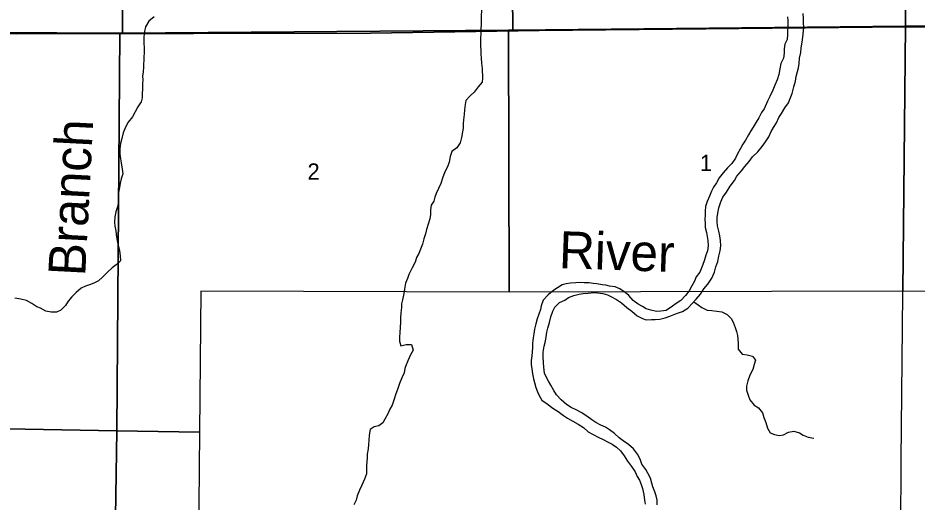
# Model space of a CAD drawing. Extents: x 1772825 to 1773716, y 1138558 to 1139032.
# Drawn here: x 1772826.846 to 1772827.997, y 1138560.526 to 1138561.147 of the extents above; entities that cross this region are included whole.
import ezdxf

# ---------------------------------------------------------------- set-up
doc = ezdxf.new("R2010")
doc.units = 0
for name, color, linetype in [('GM_X_Major_River', 7, 'Continuous'), ('GM_X_Major_River_Text', 7, 'Continuous'), ('GM_X_Minor_River', 7, 'Continuous'), ('GM_X_Minor_River_Text', 7, 'Continuous'), ('GM_X_Section', 7, 'Continuous'), ('GM_X_Section_Text', 7, 'Continuous'), ('GM_X_Township', 7, 'Continuous')]:
    doc.layers.add(name, color=color, linetype=linetype)

msp = doc.modelspace()

# ---------------------------------------------------------------- linework, layer by layer
at = {"layer": 'GM_X_Major_River'}
for points in [[(1772827.6457, 1138560.7616), (1772827.6506, 1138560.76), (1772827.6572, 1138560.7604), (1772827.662, 1138560.7603), (1772827.6682, 1138560.7607), (1772827.6749, 1138560.7625), (1772827.6806, 1138560.7646), (1772827.6873, 1138560.7672), (1772827.692, 1138560.7688), (1772827.697, 1138560.7709), (1772827.7038, 1138560.775), (1772827.7096, 1138560.7808), (1772827.7145, 1138560.7867), (1772827.7199, 1138560.7931), (1772827.7245, 1138560.7999), (1772827.7293, 1138560.8059), (1772827.7346, 1138560.8135), (1772827.7379, 1138560.8212), (1772827.7399, 1138560.828), (1772827.7424, 1138560.835), (1772827.7436, 1138560.8415), (1772827.7453, 1138560.8485), (1772827.746, 1138560.8551), (1772827.7456, 1138560.8618), (1772827.7449, 1138560.8677), (1772827.7434, 1138560.8737), (1772827.742, 1138560.8804), (1772827.7414, 1138560.8855), (1772827.7415, 1138560.8914), (1772827.7423, 1138560.8967), (1772827.7437, 1138560.9037), (1772827.7462, 1138560.9113), (1772827.7489, 1138560.9171), (1772827.7535, 1138560.9239), (1772827.7581, 1138560.9315), (1772827.7635, 1138560.9388), (1772827.7667, 1138560.9443), (1772827.7725, 1138560.9511), (1772827.7767, 1138560.9564), (1772827.7826, 1138560.9632), (1772827.7866, 1138560.9692), (1772827.7935, 1138560.9756), (1772827.7991, 1138560.9824), (1772827.8033, 1138560.9882), (1772827.8075, 1138560.9947), (1772827.8108, 1138561.0015), (1772827.8137, 1138561.0068), (1772827.8173, 1138561.0128), (1772827.8204, 1138561.0196), (1772827.8239, 1138561.0245), (1772827.8281, 1138561.0317), (1772827.8329, 1138561.0383), (1772827.835, 1138561.0436), (1772827.8373, 1138561.0504), (1772827.8395, 1138561.0587), (1772827.8416, 1138561.0659), (1772827.8426, 1138561.0722), (1772827.8444, 1138561.0782), (1772827.8454, 1138561.0832), (1772827.8465, 1138561.0887), (1772827.8471, 1138561.0953), (1772827.8485, 1138561.1027), (1772827.8491, 1138561.1089), (1772827.8501, 1138561.1158), (1772827.8513, 1138561.1224), (1772827.8524, 1138561.1347), (1772827.8522, 1138561.1412), (1772827.8521, 1138561.1467), (1772827.8514, 1138561.1527)], [(1772827.8316, 1138561.1487), (1772827.8319, 1138561.1434), (1772827.8321, 1138561.1354), (1772827.8317, 1138561.1307), (1772827.8316, 1138561.126), (1772827.831, 1138561.1193), (1772827.8281, 1138561.1133), (1772827.8273, 1138561.1076), (1772827.8271, 1138561.1017), (1772827.8263, 1138561.0955), (1772827.823, 1138561.0885), (1772827.8218, 1138561.0818), (1772827.8204, 1138561.0746), (1772827.8181, 1138561.0678), (1772827.8152, 1138561.0608), (1772827.8129, 1138561.0544), (1772827.8088, 1138561.0463), (1772827.806, 1138561.0404), (1772827.8017, 1138561.0306), (1772827.7983, 1138561.0257), (1772827.7946, 1138561.0189), (1772827.7915, 1138561.0136), (1772827.7877, 1138561.0071), (1772827.7846, 1138561.0022), (1772827.7817, 1138560.9973), (1772827.7777, 1138560.9905), (1772827.7741, 1138560.9852), (1772827.7714, 1138560.9798), (1772827.7673, 1138560.973), (1772827.7648, 1138560.9675), (1772827.7602, 1138560.9605), (1772827.7547, 1138560.9547), (1772827.7493, 1138560.9486), (1772827.7441, 1138560.9422), (1772827.7405, 1138560.9356), (1772827.7366, 1138560.9301), (1772827.7341, 1138560.925), (1772827.7318, 1138560.9186), (1772827.7285, 1138560.9118), (1772827.7264, 1138560.9054), (1772827.7262, 1138560.8993), (1772827.7259, 1138560.8944), (1772827.7255, 1138560.8892), (1772827.7259, 1138560.8835), (1772827.7262, 1138560.8784), (1772827.7277, 1138560.8721), (1772827.7288, 1138560.8668), (1772827.7295, 1138560.8617), (1772827.7298, 1138560.8551), (1772827.729, 1138560.8486), (1772827.7271, 1138560.8431), (1772827.7251, 1138560.8369), (1772827.7226, 1138560.8295), (1772827.7191, 1138560.821), (1772827.7145, 1138560.815), (1772827.7122, 1138560.8098), (1772827.7088, 1138560.8038), (1772827.7055, 1138560.7974), (1772827.7009, 1138560.7913), (1772827.695, 1138560.7849), (1772827.6891, 1138560.781), (1772827.6841, 1138560.7774), (1772827.6761, 1138560.772), (1772827.6691, 1138560.7713), (1772827.6636, 1138560.7708), (1772827.6566, 1138560.7723)], [(1772827.6566, 1138560.7723), (1772827.6507, 1138560.7743), (1772827.6458, 1138560.777), (1772827.6403, 1138560.78), (1772827.6337, 1138560.785), (1772827.6284, 1138560.7913), (1772827.6235, 1138560.7952), (1772827.6169, 1138560.7999), (1772827.6109, 1138560.8023), (1772827.6037, 1138560.8031), (1772827.5987, 1138560.8043), (1772827.594, 1138560.805), (1772827.5872, 1138560.8062), (1772827.5824, 1138560.8068), (1772827.5775, 1138560.8073), (1772827.5711, 1138560.8075), (1772827.5652, 1138560.8079), (1772827.5604, 1138560.8074), (1772827.5534, 1138560.8071), (1772827.5479, 1138560.8062), (1772827.5431, 1138560.8049), (1772827.537, 1138560.8009), (1772827.5321, 1138560.7979), (1772827.525, 1138560.7921), (1772827.5187, 1138560.7851), (1772827.516, 1138560.7781), (1772827.515, 1138560.7732), (1772827.5131, 1138560.7675), (1772827.511, 1138560.7615), (1772827.5092, 1138560.755), (1772827.5074, 1138560.7482), (1772827.5066, 1138560.7422), (1772827.5058, 1138560.7368), (1772827.505, 1138560.73), (1772827.5048, 1138560.7249), (1772827.5046, 1138560.7185), (1772827.504, 1138560.7137), (1772827.5033, 1138560.7078), (1772827.5033, 1138560.7027), (1772827.5042, 1138560.6972), (1772827.5051, 1138560.6909), (1772827.5062, 1138560.6845), (1772827.5073, 1138560.6795), (1772827.5092, 1138560.6731), (1772827.5112, 1138560.6679), (1772827.5136, 1138560.6628), (1772827.517, 1138560.6571), (1772827.5236, 1138560.6523), (1772827.531, 1138560.6469), (1772827.5376, 1138560.6427), (1772827.5448, 1138560.6372), (1772827.5497, 1138560.6339), (1772827.5567, 1138560.6302), (1772827.5633, 1138560.6264), (1772827.5701, 1138560.6222), (1772827.5763, 1138560.6166), (1772827.5827, 1138560.613), (1772827.5888, 1138560.6097), (1772827.5956, 1138560.6066), (1772827.6018, 1138560.6032), (1772827.6071, 1138560.6006), (1772827.6126, 1138560.5968), (1772827.6176, 1138560.592), (1772827.6225, 1138560.5855), (1772827.6267, 1138560.5789), (1772827.6319, 1138560.5722), (1772827.6364, 1138560.5651), (1772827.6388, 1138560.5592), (1772827.642, 1138560.5543), (1772827.6441, 1138560.5488), (1772827.6457, 1138560.5436), (1772827.6476, 1138560.5362), (1772827.6485, 1138560.529), (1772827.649, 1138560.5235)], [(1772827.6646, 1138560.5228), (1772827.6644, 1138560.5289), (1772827.6635, 1138560.5344), (1772827.6617, 1138560.5395), (1772827.6592, 1138560.546), (1772827.6579, 1138560.5508), (1772827.6559, 1138560.5572), (1772827.6527, 1138560.5635), (1772827.6499, 1138560.5683), (1772827.6448, 1138560.5751), (1772827.6426, 1138560.5812), (1772827.6396, 1138560.5877), (1772827.6344, 1138560.5946), (1772827.6278, 1138560.6003), (1772827.621, 1138560.6049), (1772827.6157, 1138560.6089), (1772827.61, 1138560.6145), (1772827.6036, 1138560.6189), (1772827.5985, 1138560.6223), (1772827.5923, 1138560.625), (1772827.586, 1138560.6285), (1772827.5809, 1138560.632), (1772827.5743, 1138560.6366), (1772827.5672, 1138560.6414), (1772827.5615, 1138560.6444), (1772827.5545, 1138560.6477), (1772827.5486, 1138560.6514), (1772827.5417, 1138560.6575), (1772827.5358, 1138560.664), (1772827.5323, 1138560.6693), (1772827.5282, 1138560.6762), (1772827.5252, 1138560.6813), (1772827.5225, 1138560.6868), (1772827.5203, 1138560.6918), (1772827.5192, 1138560.6992), (1772827.5189, 1138560.7055), (1772827.5184, 1138560.7127), (1772827.5184, 1138560.7185), (1772827.5198, 1138560.7261), (1772827.5214, 1138560.7326), (1772827.5222, 1138560.7384), (1772827.5233, 1138560.7441), (1772827.5247, 1138560.7494), (1772827.5267, 1138560.7568), (1772827.5284, 1138560.7638), (1772827.5309, 1138560.7712), (1772827.5334, 1138560.7761), (1772827.5394, 1138560.7821), (1772827.5464, 1138560.7853), (1772827.5512, 1138560.7885), (1772827.5578, 1138560.7913), (1772827.5647, 1138560.7929), (1772827.5696, 1138560.7937), (1772827.5761, 1138560.7944), (1772827.5833, 1138560.7951), (1772827.588, 1138560.7948), (1772827.5949, 1138560.7938), (1772827.6011, 1138560.7921), (1772827.606, 1138560.7894), (1772827.6123, 1138560.7859), (1772827.6189, 1138560.7819), (1772827.6257, 1138560.776), (1772827.6321, 1138560.771), (1772827.6389, 1138560.7651), (1772827.6457, 1138560.7616)]]:
    msp.add_lwpolyline(points, dxfattribs=at)
at = {"layer": 'GM_X_Minor_River'}
for points in [[(1772827.4394, 1138561.1663), (1772827.4392, 1138561.1399), (1772827.4389, 1138561.1318), (1772827.4387, 1138561.127), (1772827.4385, 1138561.1213), (1772827.4383, 1138561.1166), (1772827.4384, 1138561.1105), (1772827.4386, 1138561.1058)], [(1772827.0201, 1138561.1484), (1772827.0135, 1138561.1429), (1772827.0092, 1138561.1355), (1772827.008, 1138561.1297), (1772827.0072, 1138561.1227), (1772827.0072, 1138561.1147), (1772827.0073, 1138561.1088), (1772827.0073, 1138561.1033), (1772827.0069, 1138561.0965), (1772827.0068, 1138561.0843), (1772827.0061, 1138561.0775), (1772827.0055, 1138561.0728), (1772827.0057, 1138561.0678), (1772827.0055, 1138561.0625), (1772827.0052, 1138561.0561), (1772827.0048, 1138561.0496), (1772827.0048, 1138561.0447)], [(1772827.4386, 1138561.1058), (1772827.4389, 1138561.1006), (1772827.4392, 1138561.0957), (1772827.4396, 1138561.0889), (1772827.4403, 1138561.0822), (1772827.4409, 1138561.0697), (1772827.4403, 1138561.0648), (1772827.4352, 1138561.0586), (1772827.4302, 1138561.0521), (1772827.425, 1138561.0472), (1772827.4197, 1138561.0412), (1772827.4187, 1138561.0361), (1772827.4179, 1138561.0291), (1772827.4175, 1138561.0234), (1772827.4166, 1138561.0166), (1772827.4162, 1138561.0111), (1772827.416, 1138561.0058), (1772827.4154, 1138561.001), (1772827.4138, 1138560.9938), (1772827.4124, 1138560.9868), (1772827.408, 1138560.9806), (1772827.4017, 1138560.9759), (1772827.3994, 1138560.9693), (1772827.398, 1138560.9621), (1772827.3961, 1138560.956), (1772827.3924, 1138560.9496), (1772827.3895, 1138560.9417), (1772827.3874, 1138560.9348), (1772827.3847, 1138560.9286), (1772827.3816, 1138560.9222), (1772827.3799, 1138560.9173), (1772827.3787, 1138560.9123), (1772827.3752, 1138560.9072), (1772827.3744, 1138560.9012), (1772827.3744, 1138560.8949), (1772827.3734, 1138560.8894), (1772827.3711, 1138560.8826), (1772827.3693, 1138560.876), (1772827.3678, 1138560.8703), (1772827.3656, 1138560.8639), (1772827.3639, 1138560.857), (1772827.3615, 1138560.8508), (1772827.3594, 1138560.8449), (1772827.3563, 1138560.8398), (1772827.3546, 1138560.834), (1772827.3507, 1138560.8266), (1772827.3467, 1138560.8181), (1772827.3446, 1138560.813), (1772827.3424, 1138560.8071), (1772827.3409, 1138560.7995), (1772827.3401, 1138560.7937), (1772827.3383, 1138560.7855), (1772827.3371, 1138560.7806), (1772827.3371, 1138560.7757), (1772827.3363, 1138560.7689), (1772827.3358, 1138560.7626), (1772827.336, 1138560.7575), (1772827.3354, 1138560.7501), (1772827.3349, 1138560.7438), (1772827.3345, 1138560.7378), (1772827.3345, 1138560.7328), (1772827.3363, 1138560.7269), (1772827.343, 1138560.7282), (1772827.3498, 1138560.7282), (1772827.3519, 1138560.7213), (1772827.3486, 1138560.7151), (1772827.3453, 1138560.7075), (1772827.3432, 1138560.7024), (1772827.3412, 1138560.6975), (1772827.3403, 1138560.6922), (1772827.3377, 1138560.6856), (1772827.3346, 1138560.6782), (1772827.3321, 1138560.6708), (1772827.33, 1138560.6651), (1772827.3279, 1138560.6583), (1772827.325, 1138560.6508), (1772827.3223, 1138560.6457), (1772827.3194, 1138560.6394), (1772827.3157, 1138560.6328), (1772827.313, 1138560.6279), (1772827.3079, 1138560.6243), (1772827.302, 1138560.623), (1772827.2968, 1138560.6193), (1772827.2956, 1138560.6121), (1772827.2952, 1138560.6055), (1772827.2948, 1138560.6003), (1772827.2942, 1138560.5945), (1772827.2932, 1138560.5878), (1772827.293, 1138560.5831), (1772827.2927, 1138560.5783), (1772827.2923, 1138560.5727), (1772827.2923, 1138560.5672), (1772827.2924, 1138560.5624), (1772827.2897, 1138560.5558), (1772827.2861, 1138560.5482), (1772827.2832, 1138560.5416), (1772827.2804, 1138560.5342), (1772827.2789, 1138560.5289), (1772827.276, 1138560.5229)], [(1772827.0048, 1138561.0447), (1772827.0038, 1138561.0396), (1772826.9994, 1138561.0332), (1772826.9924, 1138561.0203), (1772826.9871, 1138561.0135), (1772826.9834, 1138561.0071), (1772826.9807, 1138560.9999), (1772826.9788, 1138560.9927), (1772826.9772, 1138560.9861), (1772826.9764, 1138560.9798), (1772826.9763, 1138560.9724), (1772826.9772, 1138560.9664), (1772826.978, 1138560.9612), (1772826.9794, 1138560.9534), (1772826.98, 1138560.9472), (1772826.9782, 1138560.9409), (1772826.9768, 1138560.9351), (1772826.9758, 1138560.9296), (1772826.9748, 1138560.9233), (1772826.9746, 1138560.9178), (1772826.9746, 1138560.9114), (1772826.9734, 1138560.9051), (1772826.9714, 1138560.8987), (1772826.9701, 1138560.8919), (1772826.9696, 1138560.8852), (1772826.9698, 1138560.8799), (1772826.9711, 1138560.874), (1772826.9718, 1138560.8693), (1772826.9725, 1138560.864), (1772826.9732, 1138560.859), (1772826.9747, 1138560.8541), (1772826.976, 1138560.8486), (1772826.9769, 1138560.8421), (1772826.9772, 1138560.8357), (1772826.9717, 1138560.8304), (1772826.9667, 1138560.8266), (1772826.9604, 1138560.8212), (1772826.9539, 1138560.8148), (1772826.9491, 1138560.8099), (1772826.944, 1138560.8074), (1772826.9387, 1138560.8054), (1772826.9324, 1138560.8032), (1772826.9267, 1138560.8008), (1772826.9204, 1138560.7951), (1772826.9147, 1138560.7893), (1772826.9103, 1138560.784), (1772826.9068, 1138560.7785), (1772826.9009, 1138560.7723), (1772826.895, 1138560.7699), (1772826.8885, 1138560.7699), (1772826.8817, 1138560.7713), (1772826.8749, 1138560.7748), (1772826.87, 1138560.7767), (1772826.8636, 1138560.7811), (1772826.8568, 1138560.7846), (1772826.8497, 1138560.7867), (1772826.8418, 1138560.7877)], [(1772827.7114, 1138560.783), (1772827.7171, 1138560.7791), (1772827.722, 1138560.776), (1772827.7288, 1138560.7725), (1772827.7347, 1138560.7719), (1772827.7408, 1138560.7713), (1772827.7474, 1138560.7701), (1772827.7544, 1138560.7667), (1772827.7595, 1138560.7619), (1772827.7621, 1138560.7571), (1772827.7643, 1138560.7501), (1772827.766, 1138560.7449), (1772827.7673, 1138560.74), (1772827.768, 1138560.7351), (1772827.7684, 1138560.7296), (1772827.7685, 1138560.7224), (1772827.7736, 1138560.7161), (1772827.78, 1138560.7152), (1772827.7867, 1138560.7135), (1772827.7904, 1138560.7082), (1772827.789, 1138560.7027), (1772827.7871, 1138560.6962), (1772827.7832, 1138560.689), (1772827.7807, 1138560.682), (1772827.7788, 1138560.675), (1772827.7791, 1138560.6699), (1772827.7812, 1138560.6633), (1772827.7834, 1138560.6574), (1772827.7887, 1138560.6507), (1772827.7943, 1138560.6472), (1772827.7996, 1138560.6407), (1772827.8014, 1138560.6348), (1772827.8039, 1138560.6282), (1772827.8061, 1138560.621), (1772827.8094, 1138560.6151), (1772827.8147, 1138560.6129), (1772827.8208, 1138560.6116), (1772827.8265, 1138560.6125), (1772827.833, 1138560.6162), (1772827.8398, 1138560.6171), (1772827.8468, 1138560.6153), (1772827.8517, 1138560.6123), (1772827.8582, 1138560.6096), (1772827.8652, 1138560.6082)]]:
    msp.add_lwpolyline(points, dxfattribs=at)
at = {"layer": 'GM_X_Section'}
for points in [[(1772827.9835, 1138561.6464), (1772828.5028, 1138561.6436), (1772828.4973, 1138561.1378), (1772827.9825, 1138561.1365), (1772827.9834, 1138561.6394)], [(1772827.4752, 1138561.6322), (1772827.9834, 1138561.6394), (1772827.9825, 1138561.1365), (1772827.4796, 1138561.1316)], [(1772826.4849, 1138561.6314), (1772826.9813, 1138561.6303), (1772826.9799, 1138561.1276), (1772826.9762, 1138561.1277), (1772826.4923, 1138561.13), (1772826.4783, 1138561.1299)], [(1772826.9813, 1138561.6303), (1772827.4752, 1138561.6322), (1772827.4796, 1138561.1316), (1772827.4741, 1138561.1315), (1772826.9799, 1138561.1276)], [(1772828.4973, 1138561.1378), (1772828.4997, 1138561.1379), (1772828.4951, 1138560.7937), (1772827.9793, 1138560.7967), (1772827.9825, 1138561.1365)], [(1772826.4923, 1138561.13), (1772826.9762, 1138561.1277), (1772826.9725, 1138560.6175), (1772826.4788, 1138560.6265)], [(1772826.9799, 1138561.1276), (1772827.4741, 1138561.1315), (1772827.4748, 1138560.7954), (1772827.0799, 1138560.7968), (1772827.0782, 1138560.6161), (1772826.9725, 1138560.6175), (1772826.9762, 1138561.1277)], [(1772827.4796, 1138561.1316), (1772827.9825, 1138561.1365), (1772827.9793, 1138560.7967), (1772827.4748, 1138560.7954), (1772827.4741, 1138561.1315)], [(1772826.4788, 1138560.6265), (1772826.9725, 1138560.6175), (1772826.9648, 1138560.1213), (1772826.4728, 1138560.1264)], [(1772826.9725, 1138560.6175), (1772827.0782, 1138560.6161), (1772827.0752, 1138560.2887), (1772827.4738, 1138560.2882), (1772827.4735, 1138560.1264), (1772826.9648, 1138560.1213)]]:
    msp.add_lwpolyline(points, close=True, dxfattribs=at)
at = {"layer": 'GM_X_Township'}
for points in [[(1772825.3579, 1138561.138), (1772825.4728, 1138561.1365), (1772825.8143, 1138561.1337), (1772825.9786, 1138561.1321), (1772826.4791, 1138561.1287), (1772826.4941, 1138561.1288), (1772826.8442, 1138561.1267), (1772827.2975, 1138561.1277), (1772827.5133, 1138561.1311), (1772827.9826, 1138561.1355), (1772827.9839, 1138561.2587)], [(1772829.265, 1138561.1343), (1772828.9351, 1138561.1362), (1772828.7389, 1138561.1358), (1772828.3739, 1138561.1358), (1772827.9826, 1138561.1355), (1772827.9839, 1138561.2587)], [(1772826.3845, 1138558.127), (1772826.9572, 1138558.1261), (1772827.5595, 1138558.1253), (1772827.5857, 1138558.1252), (1772827.9602, 1138558.1247), (1772827.9658, 1138558.8741), (1772827.9695, 1138559.3784), (1772827.9733, 1138559.6274), (1772827.9734, 1138559.8049), (1772827.972, 1138559.9153), (1772827.9742, 1138560.1264), (1772827.9761, 1138560.4021), (1772827.9772, 1138560.5798), (1772827.9826, 1138561.1355), (1772827.5133, 1138561.1311), (1772827.2975, 1138561.1277), (1772826.8442, 1138561.1267)], [(1772829.3568, 1138558.1226), (1772828.6597, 1138558.1236), (1772828.4654, 1138558.1239), (1772828.0428, 1138558.1245), (1772827.9602, 1138558.1247), (1772827.9658, 1138558.8741), (1772827.9695, 1138559.3784), (1772827.9733, 1138559.6274), (1772827.9734, 1138559.8049), (1772827.972, 1138559.9153), (1772827.9742, 1138560.1264), (1772827.9761, 1138560.4021), (1772827.9772, 1138560.5798), (1772827.9826, 1138561.1355), (1772828.3739, 1138561.1358), (1772828.7389, 1138561.1358), (1772828.9351, 1138561.1362), (1772829.265, 1138561.1343)]]:
    msp.add_lwpolyline(points, dxfattribs=at)

# ---------------------------------------------------------------- texts
at = {"layer": 'GM_X_Major_River_Text'}
msp.add_text('River', height=0.04737, rotation=358.0157, dxfattribs=at).set_placement((1772827.5383, 1138560.8264))
at = {"layer": 'GM_X_Minor_River_Text'}
msp.add_text('Branch', height=0.04737, rotation=87.0385, dxfattribs=at).set_placement((1772826.9319, 1138560.8154))
at = {"layer": 'GM_X_Section_Text'}
for s, p in [('1', (1772827.7194, 1138560.9508)), ('2', (1772827.2167, 1138560.9397))]:
    msp.add_text(s, height=0.0209, rotation=0, dxfattribs=at).set_placement(p)

doc.saveas('drawing.dxf')
